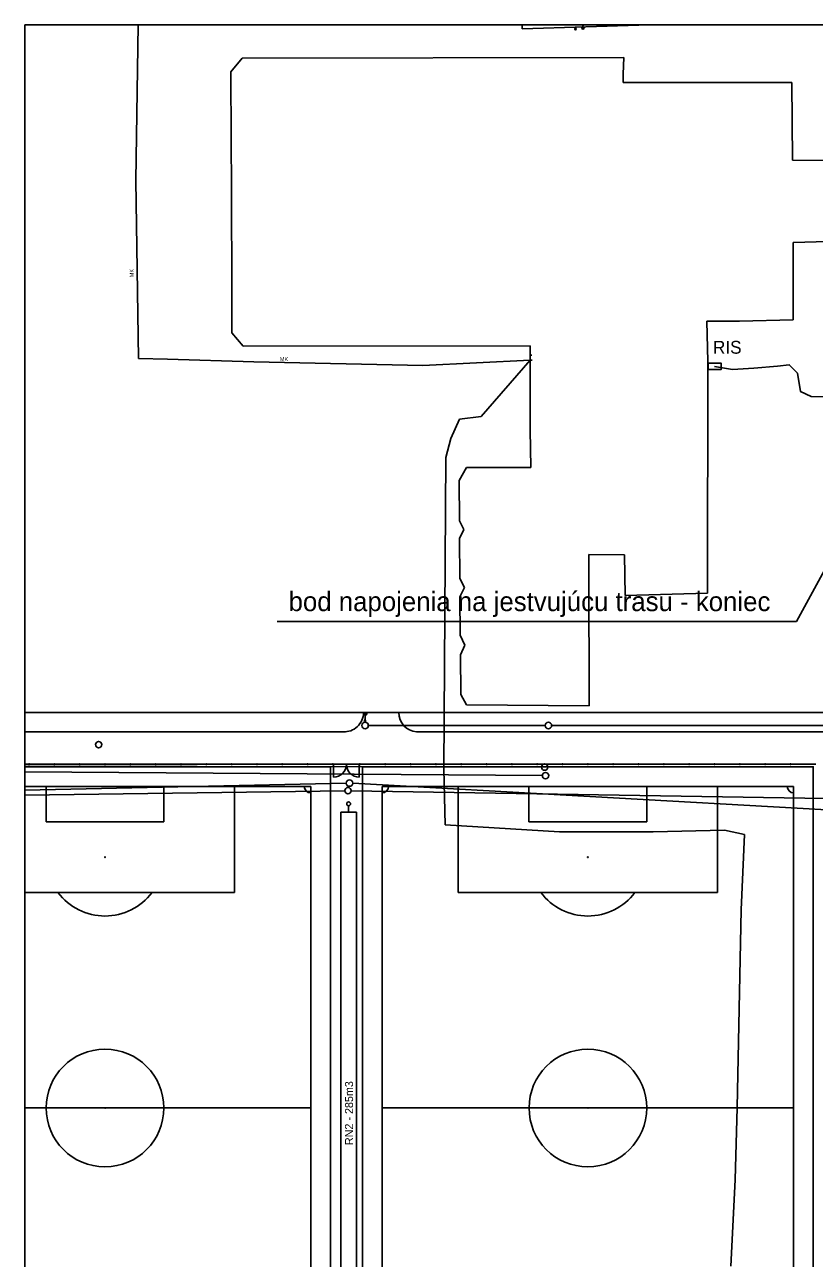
# Model space of a CAD drawing. Extents: x -264095 to -263675, y -1242370 to -1242073.
# Drawn here: x -264095.1 to -263972.3, y -1242264.4 to -1242072.5 of the extents above; entities that cross this region are included whole.
import ezdxf

# ---------------------------------------------------------------- set-up
doc = ezdxf.new("R2010")
doc.units = 0
for name, color, linetype in [('KFA_2D_JESTVUJUCE_IS_DSP', 7, 'Continuous'), ('KFA_2D_SITUACIA_DSP', 7, 'Continuous'), ('POPIS', 7, 'Continuous'), ('Pripojka_NN_pre_ORANGE_vysielac_povodna_trasa', 7, 'Continuous'), ('Pripojka_NN_pre_ORANGE_vysielac_povodna_trasa_EL_SKRINA', 7, 'Continuous'), ('RAM_NA_TLAC_A3_1-1000', 7, 'Continuous')]:
    doc.layers.add(name, color=color, linetype=linetype)

msp = doc.modelspace()

# ---------------------------------------------------------------- linework, layer by layer
at = {"layer": 'KFA_2D_JESTVUJUCE_IS_DSP'}
for p, q in [((-264077.46, -1242072.53), (-264077.8, -1242096.77)), ((-264017.73, -1242072.53), (-264017.72, -1242073.15)), ((-264017.72, -1242073.15), (-263997.93, -1242072.53)), ((-264008.41, -1242072.62), (-264008.16, -1242072.62)), ((-264008.29, -1242072.87), (-264008.29, -1242072.62)), ((-264008.43, -1242073.18), (-264008.14, -1242072.95)), ((-264077.8, -1242096.77), (-264077.43, -1242124.43)), ((-264077.43, -1242124.43), (-264072.89, -1242124.56)), ((-264072.89, -1242124.56), (-264059.47, -1242124.95)), ((-264016.21, -1242123.92), (-264016.51, -1242123.92)), ((-264016.51, -1242123.92), (-264016.5, -1242124.67)), ((-264059.47, -1242124.95), (-264033.2, -1242125.52)), ((-264033.2, -1242125.52), (-264016.5, -1242124.67)), ((-264016.5, -1242124.67), (-264024.13, -1242133.46)), ((-264016.5, -1242124.67), (-264016.2, -1242124.67)), ((-264027.51, -1242133.87), (-264028.85, -1242136.85)), ((-264024.13, -1242133.46), (-264027.51, -1242133.87)), ((-264028.85, -1242136.85), (-264029.59, -1242139.82)), ((-264029.59, -1242139.82), (-264029.91, -1242188.32)), ((-264014.74, -1242187.97), (-264095.11, -1242187.82)), ((-264014.6, -1242189.3), (-264095.11, -1242188.71)), ((-264029.91, -1242188.32), (-264029.72, -1242196.93)), ((-264045.1, -1242190.47), (-264095.11, -1242191.54)), ((-264045.33, -1242191.64), (-264095.11, -1242192.36)), ((-263970.54, -1242192.88), (-264044.33, -1242191.64)), ((-263970.37, -1242194.6), (-264044.1, -1242190.48)), ((-264029.72, -1242196.93), (-264011.93, -1242198.06)), ((-264011.93, -1242198.06), (-263997.36, -1242198.03)), ((-263997.36, -1242198.03), (-263986.29, -1242197.77)), ((-263986.29, -1242197.77), (-263983.14, -1242198.47)), ((-263983.14, -1242198.47), (-263983.69, -1242210.18)), ((-263983.69, -1242210.18), (-263984.29, -1242240.93)), ((-263984.29, -1242240.93), (-263984.63, -1242252.16)), ((-263984.63, -1242252.16), (-263985.27, -1242265.6))]:
    msp.add_line(p, q, dxfattribs=at)
for centre, radius in [((-264009.44, -1242073.2), 0.125), ((-264008.29, -1242073.06), 0.188), ((-264083.61, -1242184.48), 0.5), ((-264014.24, -1242187.97), 0.5), ((-264014.1, -1242189.3), 0.5), ((-264044.83, -1242191.63), 0.5), ((-264044.6, -1242190.46), 0.5)]:
    msp.add_circle(centre, radius, dxfattribs=at)
at = {"layer": 'KFA_2D_SITUACIA_DSP'}
for p, q in [((-264063.06, -1242079.88), (-264061.28, -1242077.73)), ((-264061.28, -1242077.73), (-264001.95, -1242077.64)), ((-264002.01, -1242080.21), (-264001.95, -1242077.64)), ((-264063.05, -1242082.02), (-264063.06, -1242079.88)), ((-264002.04, -1242081.51), (-264002.01, -1242080.21)), ((-264063.02, -1242088.27), (-264063.05, -1242082.02)), ((-263975.78, -1242081.51), (-264002.04, -1242081.51)), ((-263975.78, -1242081.51), (-263975.68, -1242093.61)), ((-264063.02, -1242088.27), (-264062.89, -1242112.12)), ((-263970.24, -1242093.63), (-263975.68, -1242093.61)), ((-263975.61, -1242118.44), (-263975.57, -1242106.38)), ((-263970.22, -1242106.22), (-263975.57, -1242106.38)), ((-264062.89, -1242112.12), (-264062.88, -1242118.3)), ((-264062.88, -1242120.44), (-264062.88, -1242118.3)), ((-263989, -1242118.61), (-263983.93, -1242118.61)), ((-263988.88, -1242124.89), (-263989, -1242118.61)), ((-263983.93, -1242118.61), (-263975.61, -1242118.44)), ((-264061.11, -1242122.5), (-264062.88, -1242120.44)), ((-264016.48, -1242122.48), (-264061.11, -1242122.5)), ((-264016.48, -1242122.48), (-264016.47, -1242135.53)), ((-263988.88, -1242124.89), (-263988.91, -1242160.93)), ((-264016.38, -1242141.37), (-264016.47, -1242135.53)), ((-264027.55, -1242143.43), (-264026.42, -1242141.41)), ((-264016.38, -1242141.37), (-264026.42, -1242141.41)), ((-264027.55, -1242143.43), (-264027.5, -1242149.68)), ((-264027.5, -1242149.68), (-264026.79, -1242151.05)), ((-264026.79, -1242151.05), (-264027.48, -1242152.43)), ((-264027.48, -1242152.43), (-264027.43, -1242158.63)), ((-264007.37, -1242157.14), (-264007.36, -1242154.93)), ((-264001.8, -1242154.96), (-264007.36, -1242154.93)), ((-264001.73, -1242161.29), (-264001.8, -1242154.96)), ((-264007.34, -1242178.42), (-264007.37, -1242157.14)), ((-264027.43, -1242158.63), (-264026.72, -1242160.07)), ((-264027.41, -1242161.52), (-264026.72, -1242160.07)), ((-263988.91, -1242160.93), (-264001.73, -1242161.29)), ((-264027.41, -1242161.52), (-264027.36, -1242167.48)), ((-264026.65, -1242168.99), (-264027.36, -1242167.48)), ((-264026.65, -1242168.99), (-264027.34, -1242170.52)), ((-264027.34, -1242170.52), (-264027.29, -1242176.68)), ((-264026.37, -1242178.31), (-264027.29, -1242176.68)), ((-264026.37, -1242178.31), (-264007.34, -1242178.42)), ((-264077.23, -1242179.48), (-264095.11, -1242179.48)), ((-264095.11, -1242179.48), (-263959.47, -1242179.48)), ((-263959.47, -1242179.48), (-264095.11, -1242179.48)), ((-263959.47, -1242179.48), (-264077.23, -1242179.48)), ((-264042.42, -1242179.48), (-264041.92, -1242179.48)), ((-264042.42, -1242179.77), (-264042.42, -1242179.48)), ((-264042.42, -1242179.48), (-264041.92, -1242179.77)), ((-264042.42, -1242179.48), (-264041.92, -1242179.77)), ((-264041.92, -1242179.48), (-264042.42, -1242179.48)), ((-264041.92, -1242179.77), (-264042.42, -1242179.77)), ((-264042.17, -1242179.97), (-264042.17, -1242181)), ((-264041.92, -1242179.48), (-264041.92, -1242179.77)), ((-264041.92, -1242179.77), (-264041.92, -1242179.48)), ((-264041.67, -1242181.5), (-264014.16, -1242181.5)), ((-264013.16, -1242181.5), (-263964.16, -1242181.5)), ((-264045.2, -1242182.48), (-264095.11, -1242182.48)), ((-263960.12, -1242182.48), (-264034.16, -1242182.48)), ((-263972.07, -1242187.53), (-264095.11, -1242187.53)), ((-264095.11, -1242294.03), (-264095.11, -1242187.93)), ((-264095.11, -1242187.93), (-264047.57, -1242187.93)), ((-264094.37, -1242187.53), (-264094.49, -1242187.53)), ((-264094.43, -1242187.59), (-264094.43, -1242187.47)), ((-264090.44, -1242187.53), (-264090.56, -1242187.53)), ((-264090.5, -1242187.59), (-264090.5, -1242187.47)), ((-264086.5, -1242187.53), (-264086.62, -1242187.53)), ((-264086.56, -1242187.59), (-264086.56, -1242187.47)), ((-264082.56, -1242187.53), (-264082.68, -1242187.53)), ((-264082.62, -1242187.59), (-264082.62, -1242187.47)), ((-264078.62, -1242187.53), (-264078.74, -1242187.53)), ((-264078.68, -1242187.59), (-264078.68, -1242187.47)), ((-264074.68, -1242187.53), (-264074.8, -1242187.53)), ((-264074.74, -1242187.59), (-264074.74, -1242187.47)), ((-264070.74, -1242187.53), (-264070.86, -1242187.53)), ((-264070.8, -1242187.59), (-264070.8, -1242187.47)), ((-264066.8, -1242187.53), (-264066.92, -1242187.53)), ((-264066.86, -1242187.59), (-264066.86, -1242187.47)), ((-264062.86, -1242187.53), (-264062.98, -1242187.53)), ((-264062.92, -1242187.59), (-264062.92, -1242187.47)), ((-264058.92, -1242187.53), (-264059.04, -1242187.53)), ((-264058.98, -1242187.59), (-264058.98, -1242187.47)), ((-264054.99, -1242187.53), (-264055.11, -1242187.53)), ((-264055.05, -1242187.59), (-264055.05, -1242187.47)), ((-264051.05, -1242187.53), (-264051.17, -1242187.53)), ((-264051.11, -1242187.59), (-264051.11, -1242187.47)), ((-264047.57, -1242187.93), (-264047.57, -1242294.03)), ((-264047.11, -1242187.53), (-264047.23, -1242187.53)), ((-264047.17, -1242187.59), (-264047.17, -1242187.47)), ((-264047.07, -1242187.53), (-264047.07, -1242189.53)), ((-264044.57, -1242187.53), (-264045.57, -1242187.53)), ((-264043.07, -1242187.53), (-264043.07, -1242189.53)), ((-264042.91, -1242187.53), (-264043.03, -1242187.53)), ((-264042.97, -1242187.59), (-264042.97, -1242187.47)), ((-264039.09, -1242187.53), (-264038.97, -1242187.53)), ((-264039.03, -1242187.59), (-264039.03, -1242187.47)), ((-264035.15, -1242187.53), (-264035.03, -1242187.53)), ((-264035.09, -1242187.59), (-264035.09, -1242187.47)), ((-264031.21, -1242187.53), (-264031.09, -1242187.53)), ((-264031.15, -1242187.59), (-264031.15, -1242187.47)), ((-264027.27, -1242187.53), (-264027.15, -1242187.53)), ((-264027.21, -1242187.59), (-264027.21, -1242187.47)), ((-264023.33, -1242187.53), (-264023.21, -1242187.53)), ((-264023.27, -1242187.59), (-264023.27, -1242187.47)), ((-264019.39, -1242187.53), (-264019.27, -1242187.53)), ((-264019.33, -1242187.59), (-264019.33, -1242187.47)), ((-264015.46, -1242187.53), (-264015.34, -1242187.53)), ((-264015.4, -1242187.59), (-264015.4, -1242187.47)), ((-264011.52, -1242187.53), (-264011.4, -1242187.53)), ((-264011.46, -1242187.59), (-264011.46, -1242187.47)), ((-264007.58, -1242187.53), (-264007.46, -1242187.53)), ((-264007.52, -1242187.59), (-264007.52, -1242187.47)), ((-264003.64, -1242187.53), (-264003.52, -1242187.53)), ((-264003.58, -1242187.59), (-264003.58, -1242187.47)), ((-263999.7, -1242187.53), (-263999.58, -1242187.53)), ((-263999.64, -1242187.59), (-263999.64, -1242187.47)), ((-263995.76, -1242187.53), (-263995.64, -1242187.53)), ((-263995.7, -1242187.59), (-263995.7, -1242187.47)), ((-263991.82, -1242187.53), (-263991.7, -1242187.53)), ((-263991.76, -1242187.59), (-263991.76, -1242187.47)), ((-263987.88, -1242187.53), (-263987.76, -1242187.53)), ((-263987.82, -1242187.59), (-263987.82, -1242187.47)), ((-263983.94, -1242187.53), (-263983.82, -1242187.53)), ((-263983.88, -1242187.59), (-263983.88, -1242187.47)), ((-263980.01, -1242187.53), (-263979.89, -1242187.53)), ((-263979.95, -1242187.59), (-263979.95, -1242187.47)), ((-263976.07, -1242187.53), (-263975.95, -1242187.53)), ((-263976.01, -1242187.59), (-263976.01, -1242187.47)), ((-264050.62, -1242190.98), (-264095.11, -1242190.98)), ((-264091.78, -1242190.98), (-264091.78, -1242196.48)), ((-264073.46, -1242196.48), (-264073.46, -1242190.98)), ((-264062.46, -1242190.98), (-264062.46, -1242207.48)), ((-264050.62, -1242290.98), (-264050.62, -1242190.98)), ((-263975.52, -1242190.98), (-264039.52, -1242190.98)), ((-264039.52, -1242190.98), (-264039.52, -1242290.98)), ((-264027.68, -1242207.48), (-264027.68, -1242190.98)), ((-264016.68, -1242190.98), (-264016.68, -1242196.48)), ((-263998.36, -1242196.48), (-263998.36, -1242190.98)), ((-263987.36, -1242190.98), (-263987.36, -1242207.48)), ((-263975.52, -1242290.98), (-263975.52, -1242190.98)), ((-264043.53, -1242194.98), (-264045.93, -1242194.98)), ((-264045.93, -1242194.98), (-264045.93, -1242293.98)), ((-264044.73, -1242194.98), (-264044.73, -1242193.98)), ((-264043.53, -1242293.98), (-264043.53, -1242194.98)), ((-264091.78, -1242196.48), (-264073.46, -1242196.48)), ((-264016.68, -1242196.48), (-263998.36, -1242196.48)), ((-264062.46, -1242207.48), (-264095.11, -1242207.48)), ((-263987.36, -1242207.48), (-264027.68, -1242207.48)), ((-264050.62, -1242240.98), (-264095.11, -1242240.98)), ((-263975.52, -1242240.98), (-264039.52, -1242240.98))]:
    msp.add_line(p, q, dxfattribs=at)
msp.add_lwpolyline([(-264042.57, -1242294.03), (-263972.47, -1242294.03), (-263972.47, -1242187.93), (-264042.57, -1242187.93)], close=True, dxfattribs=at)
for centre, radius in [((-264042.17, -1242179.87), 0.1), ((-264042.17, -1242181.5), 0.5), ((-264013.66, -1242181.5), 0.5), ((-264094.43, -1242187.53), 0.06), ((-264090.5, -1242187.53), 0.06), ((-264086.56, -1242187.53), 0.06), ((-264082.62, -1242187.53), 0.06), ((-264078.68, -1242187.53), 0.06), ((-264074.74, -1242187.53), 0.06), ((-264070.8, -1242187.53), 0.06), ((-264066.86, -1242187.53), 0.06), ((-264062.92, -1242187.53), 0.06), ((-264058.98, -1242187.53), 0.06), ((-264055.05, -1242187.53), 0.06), ((-264051.11, -1242187.53), 0.06), ((-264047.17, -1242187.53), 0.06), ((-264042.97, -1242187.53), 0.06), ((-264039.03, -1242187.53), 0.06), ((-264035.09, -1242187.53), 0.06), ((-264031.15, -1242187.53), 0.06), ((-264027.21, -1242187.53), 0.06), ((-264023.27, -1242187.53), 0.06), ((-264019.33, -1242187.53), 0.06), ((-264015.4, -1242187.53), 0.06), ((-264011.46, -1242187.53), 0.06), ((-264007.52, -1242187.53), 0.06), ((-264003.58, -1242187.53), 0.06), ((-263999.64, -1242187.53), 0.06), ((-263995.7, -1242187.53), 0.06), ((-263991.76, -1242187.53), 0.06), ((-263987.82, -1242187.53), 0.06), ((-263983.88, -1242187.53), 0.06), ((-263979.95, -1242187.53), 0.06), ((-263976.01, -1242187.53), 0.06), ((-264044.73, -1242193.68), 0.3), ((-264082.62, -1242201.98), 0.06), ((-264007.52, -1242201.98), 0.06)]:
    msp.add_circle(centre, radius, dxfattribs=at)
for centre, radius, start, end in [((-264045.41, -1242179.5), 2.99, 266.0314, 0.25), ((-264033.95, -1242179.5), 2.99, 179.75, 266.0314), ((-264042.17, -1242180.74), 0.125, 0, 180), ((-264042.17, -1242180.74), 0.125, 180, 0), ((-264047.07, -1242187.53), 2, 270, 360), ((-264043.07, -1242187.53), 2, 180, 270), ((-264050.62, -1242190.98), 1, 180, 270), ((-264039.52, -1242190.98), 1, 270, 360), ((-263975.52, -1242190.98), 1, 180, 270), ((-264082.62, -1242201.98), 0.0303, 90, 270), ((-264082.62, -1242201.98), 0.0303, 270, 90), ((-264007.52, -1242201.98), 0.0303, 90, 270), ((-264007.52, -1242201.98), 0.0303, 270, 90), ((-264082.62, -1242201.98), 9.15, 216.9482, 323.0518), ((-264007.52, -1242201.98), 9.15, 216.9482, 323.0518), ((-264082.62, -1242240.98), 9.15, 360, 180), ((-264007.52, -1242240.98), 9.15, 360, 180), ((-264082.62, -1242240.98), 9.15, 180, 360), ((-264082.62, -1242240.98), 0.0605, 90, 270), ((-264082.62, -1242240.98), 0.0605, 270, 90), ((-264007.52, -1242240.98), 9.15, 180, 360), ((-264007.52, -1242240.98), 0.0605, 90, 270), ((-264007.52, -1242240.98), 0.0605, 270, 90)]:
    msp.add_arc(centre, radius, start, end, dxfattribs=at)
at = {"layer": 'POPIS'}
for p, q in [((-263954.32, -1242127.18), (-263975.07, -1242165.35)), ((-263975.07, -1242165.35), (-264055.83, -1242165.35))]:
    msp.add_line(p, q, dxfattribs=at)
at = {"layer": 'Pripojka_NN_pre_ORANGE_vysielac_povodna_trasa'}
msp.add_lwpolyline([(-263969.06, -1242130.43), (-263972.79, -1242130.35), (-263974.43, -1242129.59), (-263974.92, -1242126.7), (-263976.2, -1242125.42), (-263978.02, -1242125.62), (-263981.69, -1242125.92), (-263985.03, -1242126.13), (-263987.8, -1242125.66)], dxfattribs=at)
at = {"layer": 'Pripojka_NN_pre_ORANGE_vysielac_povodna_trasa_EL_SKRINA'}
msp.add_lwpolyline([(-263988.8, -1242125.16), (-263986.8, -1242125.16), (-263986.8, -1242126.16), (-263988.8, -1242126.16)], close=True, dxfattribs=at)
at = {"layer": 'RAM_NA_TLAC_A3_1-1000'}
msp.add_lwpolyline([(-264095.11, -1242072.53), (-263675.11, -1242072.53), (-263675.11, -1242369.53), (-264095.11, -1242369.53)], close=True, dxfattribs=at)

# ---------------------------------------------------------------- texts
at = {"layer": 'KFA_2D_JESTVUJUCE_IS_DSP'}
msp.add_text('MK', height=0.625, rotation=90, dxfattribs=at).set_placement((-264078.15, -1242111.8))
msp.add_text('MK', height=0.625, dxfattribs=at).set_placement((-264055.42, -1242124.85))
at = {"layer": 'KFA_2D_SITUACIA_DSP'}
msp.add_text('RN2 - 285m3', height=1.25, rotation=90, dxfattribs=at).set_placement((-264044.04, -1242246.75))
at = {"layer": 'POPIS'}
msp.add_text('bod napojenia na jestvujúcu trasu - koniec', height=3, dxfattribs=at).set_placement((-264054.07, -1242163.72))
at = {"layer": 'Pripojka_NN_pre_ORANGE_vysielac_povodna_trasa_EL_SKRINA'}
msp.add_text('RIS', height=2, dxfattribs=at).set_placement((-263988.07, -1242123.69))

doc.saveas('drawing.dxf')
